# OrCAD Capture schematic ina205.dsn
size A
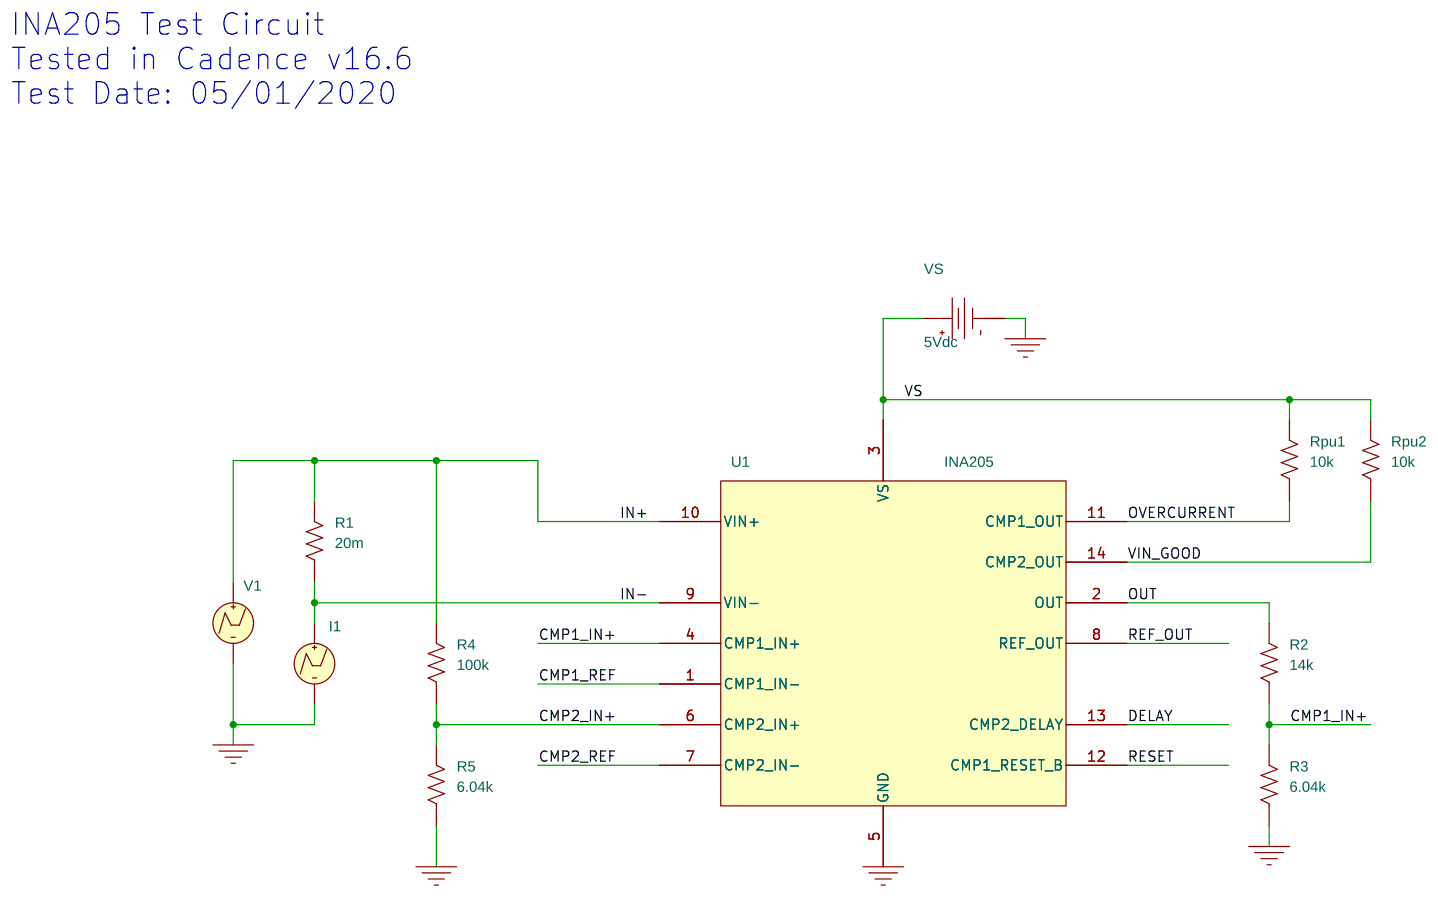
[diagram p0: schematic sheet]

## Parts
I1  IPWL
R1  20m  [AX/RC05]
R2  14k  [AX/RC05]
R3  6.04k  [AX/RC05]
R4  100k  [AX/RC05]
R5  6.04k  [AX/RC05]
Rpu1  10k  [AX/RC05]
Rpu2  10k  [AX/RC05]
U1  INA205
V1  VPWL
VS  VDC

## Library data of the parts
I1 = IPWL: I1: 0; I2: 2.5; T1: 0; T2: 2m
R1-R5 Rpu1 Rpu2 = R
U1 = INA205
V1 = VPWL: T1: 0; T2: 500u; V1: 0; V2: 12
VS = VDC: DC: 5Vdc

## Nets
VIN_GOOD: Rpu2.1 U1.14(CMP2_OUT)
0: I1.2(-) R3.1 R5.1 U1.5(GND) V1.2(-) VS.1(-)
CMP1_IN+: R2.1 R3.2 U1.4(CMP1_IN+)
CMP1_REF: U1.1(CMP1_IN-)
CMP2_IN+: R4.1 R5.2 U1.6(CMP2_IN+)
CMP2_REF: U1.7(CMP2_IN-)
DELAY: U1.13(CMP2_DELAY)
IN+: R1.2 R4.2 U1.10(VIN+) V1.1(+)
IN-: I1.1(+) R1.1 U1.9(VIN-)
OUT: R2.2 U1.2(OUT)
OVERCURRENT: Rpu1.1 U1.11(CMP1_OUT)
REF_OUT: U1.8(REF_OUT)
RESET: U1.12(CMP1_RESET_B)
VS: Rpu1.2 Rpu2.2 U1.3(VS) VS.0(+)

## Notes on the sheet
- INA205 Test Circuit
  Tested in Cadence v16.6
  Test Date: 05/01/2020
